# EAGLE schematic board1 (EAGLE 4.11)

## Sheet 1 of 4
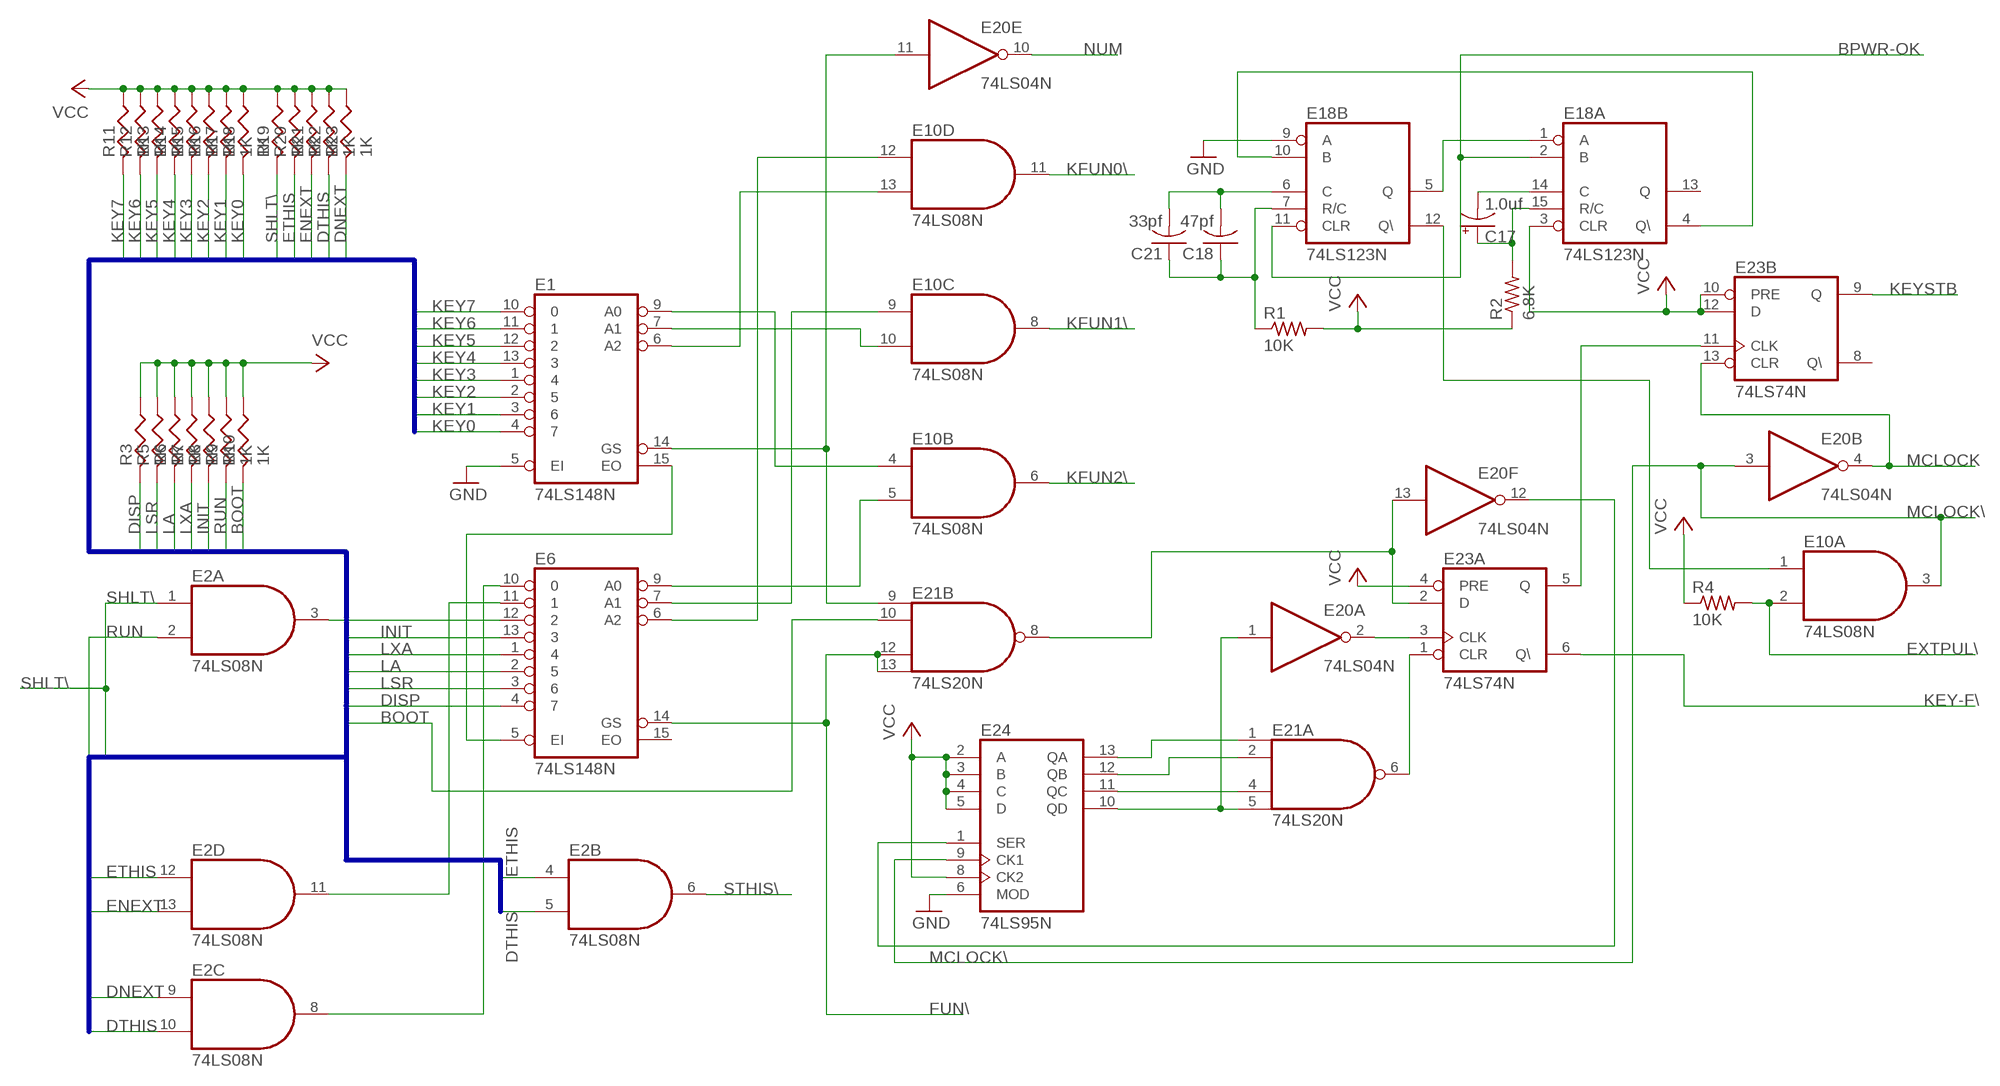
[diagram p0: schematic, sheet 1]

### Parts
C17  1.0uf  CPOL-USE15-5AXIAL  [E15-5]
C18  47pf  C-US050-025X075  [C050-025X075]
C21  33pf  C-US050-025X075  [C050-025X075]
E1  74LS148N  [DIL16]
E2  74LS08N  [DIL14]
E6  74LS148N  [DIL16]
E10  74LS08N  [DIL14]
E18  74LS123N  [DIL16]
E20  74LS04N  [DIL14]
E21  74LS20N  [DIL14]
E23  74LS74N  [DIL14]
E24  74LS95N  [DIL14]
R1  10K  R-US_0207/10  [0207/10]
R2  6.8K  R-US_0207/10  [0207/10]
R3  1K  RESUS-10  [R-10]
R4  10K  R-US_0207/10  [0207/10]
R5  1K  RESUS-10  [R-10]
R6  1K  RESUS-10  [R-10]
R7  1K  RESUS-10  [R-10]
R8  1K  RESUS-10  [R-10]
R9  1K  RESUS-10  [R-10]
R10  1K  RESUS-10  [R-10]
R11  1K  RESUS-10  [R-10]
R12  1K  RESUS-10  [R-10]
R13  1K  RESUS-10  [R-10]
R14  1K  RESUS-10  [R-10]
R15  1K  RESUS-10  [R-10]
R16  1K  RESUS-10  [R-10]
R17  1K  RESUS-10  [R-10]
R18  1K  RESUS-10  [R-10]
R19  1K  RESUS-10  [R-10]
R20  1K  RESUS-10  [R-10]
R21  1K  RESUS-10  [R-10]
R22  1K  RESUS-10  [R-10]
R23  1K  RESUS-10  [R-10]

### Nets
BOOT: E21.10(B:I1) R10.2 ; also sheet 4
BPWR-OK: E18.2(A:B) E18.11(B:CLR) ; also sheet 3
DISP: E6.4 R3.2 ; also sheet 4
DNEXT: E2.9(C:I0) R23.2 ; also sheet 4
DTHIS: E2.5(B:I1) E2.10(C:I1) R22.2 ; also sheet 4
ENEXT: E2.13(D:I1) R21.2 ; also sheet 4
ETHIS: E2.4(B:I0) E2.12(D:I0) R20.2 ; also sheet 4
EXTPUL\: E10.2(A:I1) R4.2 ; also sheet 3
FUN\: E6.14(GS) E21.12(B:I2) E21.13(B:I3) ; also sheet 3
GND [Supply]: E1.5(EI) E18.9(B:A) E24.6(MOD) ; also sheet 2,3,4
INIT: E6.13 R8.2 ; also sheet 4
KEY0: E1.4 R18.2 ; also sheet 4
KEY1: E1.3 R17.2 ; also sheet 4
KEY2: E1.2 R16.2 ; also sheet 4
KEY3: E1.1 R15.2 ; also sheet 4
KEY4: E1.13 R14.2 ; also sheet 4
KEY5: E1.12 R13.2 ; also sheet 4
KEY6: E1.11 R12.2 ; also sheet 4
KEY7: E1.10 R11.2 ; also sheet 4
KEY-F\: E23.6(A:Q\) ; also sheet 3
KEYSTB: E23.9(B:Q) ; also sheet 3
KFUN0\: E10.11(D:O) ; also sheet 3
KFUN1\: E10.8(C:O) ; also sheet 3
KFUN2\: E10.6(B:O) ; also sheet 3
LA: E6.2 R6.2 ; also sheet 4
LSR: E6.3 R5.2 ; also sheet 4
LXA: E6.1 R7.2 ; also sheet 4
MCLOCK: E20.4(B:O) E23.13(B:CLR) ; also sheet 2
MCLOCK\: E10.3(A:O) E20.3(B:I) E24.9(CK1) ; also sheet 3
N$1: E1.6(A2) E10.13(D:I1)
N$2: E1.7(A1) E10.10(C:I1)
N$3: E1.9(A0) E10.4(B:I0)
N$4: E1.14(GS) E20.11(E:I) E21.9(B:I0)
N$5: E6.6(A2) E10.12(D:I0)
N$6: E6.7(A1) E10.9(C:I0)
N$7: E6.9(A0) E10.5(B:I1)
N$8: E1.15(EO) E6.5(EI)
N$9: E21.1(A:I0) E24.13(QA)
N$10: E21.2(A:I1) E24.12(QB)
N$11: E21.4(A:I2) E24.11(QC)
N$12: E20.1(A:I) E21.5(A:I3) E24.10(QD)
N$13: E21.6(A:O) E23.1(A:CLR)
N$14: E20.2(A:O) E23.3(A:CLK)
N$15: E20.13(F:I) E21.8(B:O) E23.2(A:D)
N$16: E20.12(F:O) E24.1(SER)
N$17: E23.5(A:Q) E23.11(B:CLK)
N$18: E18.1(A:A) E18.5(B:Q)
N$19: C18.1 C21.1 E18.7(B:R/C) R1.1
N$20: C17.+ E18.15(A:R/C) R2.2
N$21: C18.2 C21.2 E18.6(B:C)
N$22: C17.- E18.14(A:C)
N$23: E2.3(A:O) E6.12
N$24: E18.4(A:Q\) E18.10(B:B)
N$25: E2.11(D:O) E6.11
N$26: E2.8(C:O) E6.10
N$27: E10.1(A:I0) E18.12(B:Q\)
NUM: E20.10(E:O) ; also sheet 3
RUN: E2.2(A:I1) R9.2 ; also sheet 4
SHLT\: E2.1(A:I0) R19.2 ; also sheet 3,4
STHIS\: E2.6(B:O) ; also sheet 3
VCC [Supply]: E18.3(A:CLR) E23.4(A:PRE) E23.10(B:PRE) E23.12(B:D) E24.2(A) E24.3(B) E24.4(C) E24.5(D) E24.8(CK2) R1.2 R2.1 R3.1 R4.1 R5.1 R6.1 R7.1 R8.1 R9.1 R10.1 R11.1 R12.1 R13.1 R14.1 R15.1 R16.1 R17.1 R18.1 R19.1 R20.1 R21.1 R22.1 R23.1 ; also sheet 2,3
Unconnected: E6.15(EO) E18.13(A:Q) E20.5(C:I) E20.6(C:O) E20.8(D:O) E20.9(D:I) E23.8(B:Q\)

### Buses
KEY[0..7],DISP,LSR,LA,LXA,INIT,RUN,BOOT,HLT\,ETHIS,ENEXT,DTHIS,DNEXT

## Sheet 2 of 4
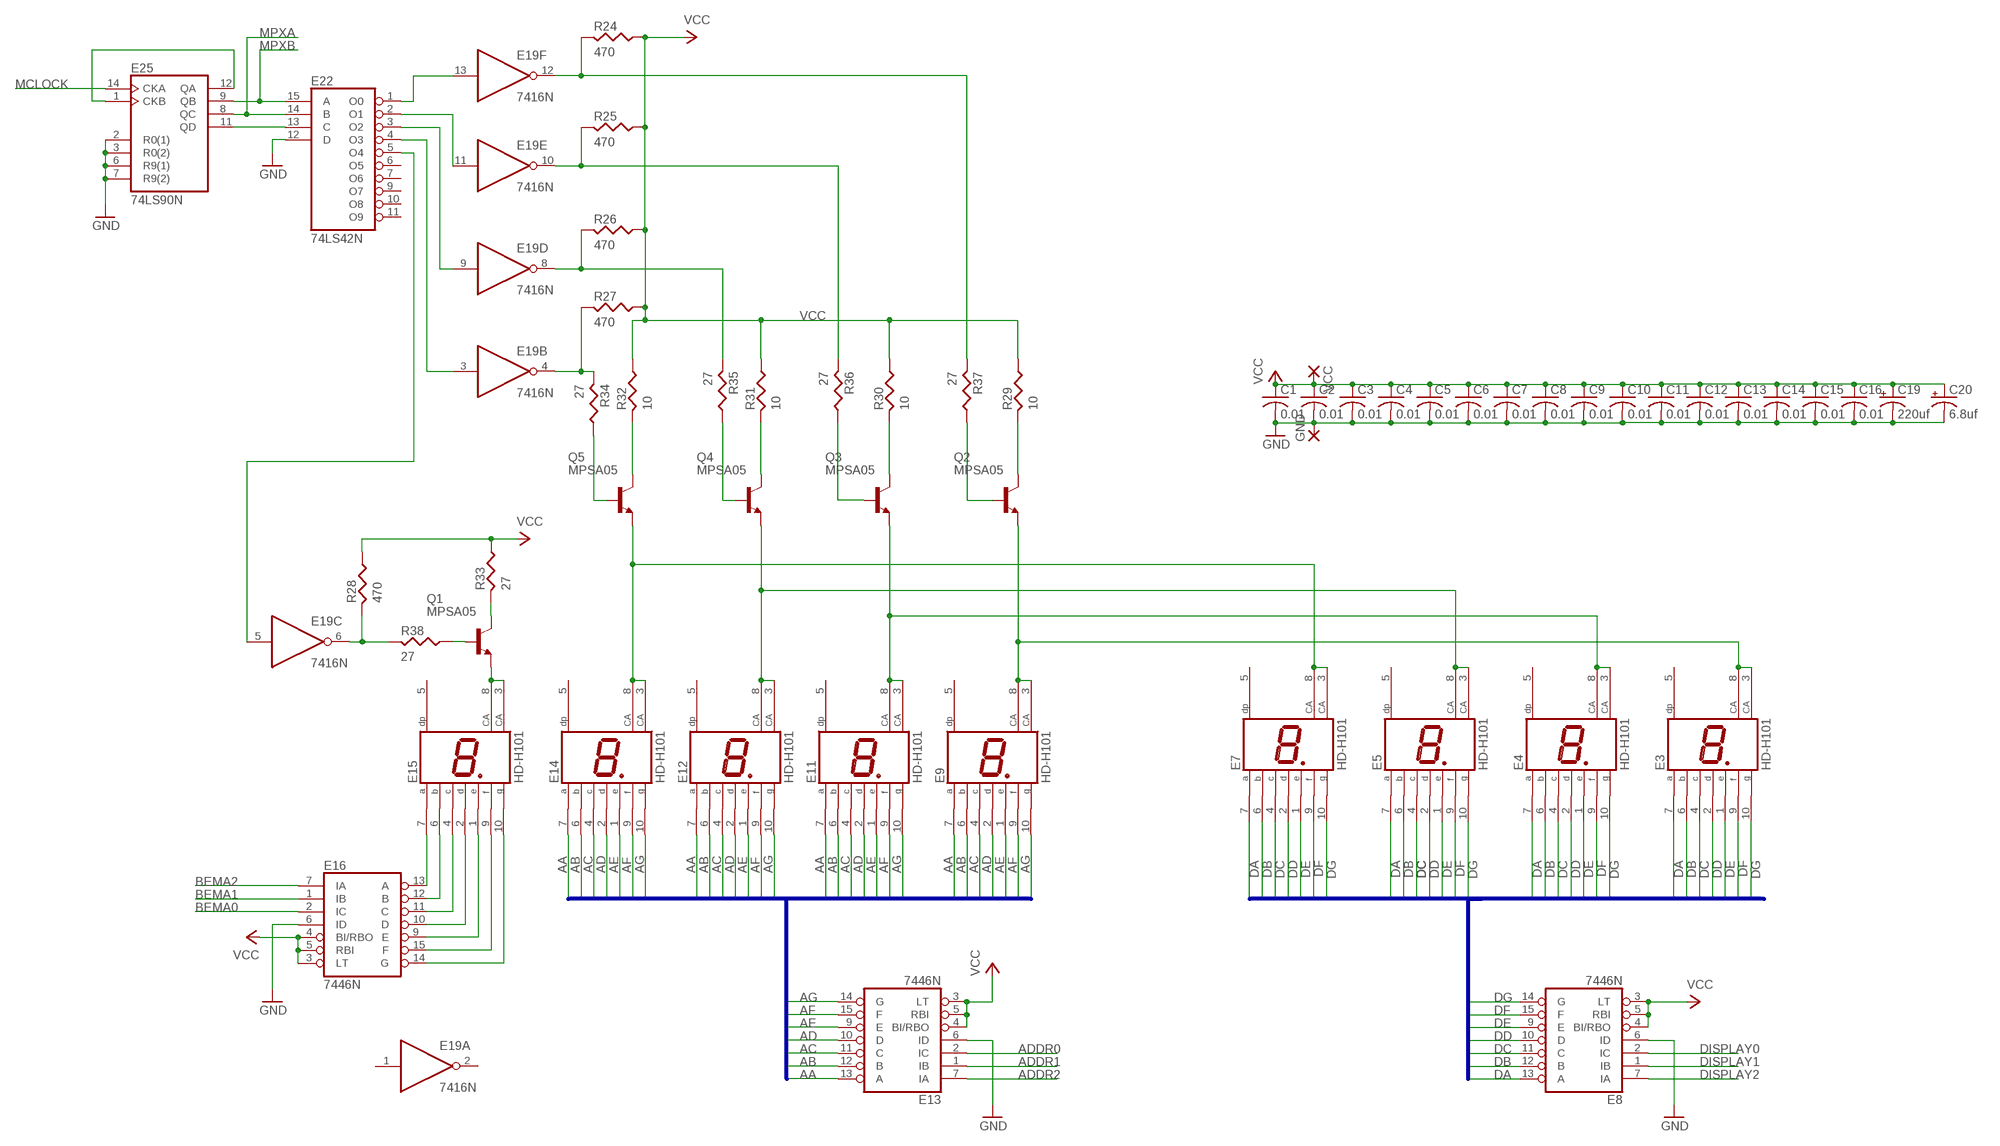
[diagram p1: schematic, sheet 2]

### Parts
C1  0.01  C-US050-025X075  [C050-025X075]
C2  0.01  C-US050-025X075  [C050-025X075]
C3  0.01  C-US050-025X075  [C050-025X075]
C4  0.01  C-US050-025X075  [C050-025X075]
C5  0.01  C-US050-025X075  [C050-025X075]
C6  0.01  C-US050-025X075  [C050-025X075]
C7  0.01  C-US050-025X075  [C050-025X075]
C8  0.01  C-US050-025X075  [C050-025X075]
C9  0.01  C-US050-025X075  [C050-025X075]
C10  0.01  C-US050-025X075  [C050-025X075]
C11  0.01  C-US050-025X075  [C050-025X075]
C12  0.01  C-US050-025X075  [C050-025X075]
C13  0.01  C-US050-025X075  [C050-025X075]
C14  0.01  C-US050-025X075  [C050-025X075]
C15  0.01  C-US050-025X075  [C050-025X075]
C16  0.01  C-US050-025X075  [C050-025X075]
C19  220uf  CPOL-USE22-6AXIAL  [E22-6]
C20  6.8uf  CPOL-USE22-6AXIAL  [E22-6]
E3  HD-H101  [HDSP-M]
E4  HD-H101  [HDSP-M]
E5  HD-H101  [HDSP-M]
E7  HD-H101  [HDSP-M]
E8  7446N  [DIL16]
E9  HD-H101  [HDSP-M]
E11  HD-H101  [HDSP-M]
E12  HD-H101  [HDSP-M]
E13  7446N  [DIL16]
E14  HD-H101  [HDSP-M]
E15  HD-H101  [HDSP-M]
E16  7446N  [DIL16]
E19  7416N  [DIL14]
E22  74LS42N  [DIL16]
E25  74LS90N  [DIL14]
GND  3,81/1,4  [3,81/1,4]
Q1  MPSA05  2N2222A  [TO18]
Q2  MPSA05  2N2222A  [TO18]
Q3  MPSA05  2N2222A  [TO18]
Q4  MPSA05  2N2222A  [TO18]
Q5  MPSA05  2N2222A  [TO18]
R24  470  RESUS-10  [R-10]
R25  470  RESUS-10  [R-10]
R26  470  RESUS-10  [R-10]
R27  470  RESUS-10  [R-10]
R28  470  RESUS-10  [R-10]
R29  10  RESUS-10  [R-10]
R30  10  RESUS-10  [R-10]
R31  10  RESUS-10  [R-10]
R32  10  RESUS-10  [R-10]
R33  27  RESUS-10  [R-10]
R34  27  RESUS-10  [R-10]
R35  27  RESUS-10  [R-10]
R36  27  RESUS-10  [R-10]
R37  27  RESUS-10  [R-10]
R38  27  RESUS-10  [R-10]
VCC  3,81/1,4  [3,81/1,4]

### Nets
AA: E9.7(A) E11.7(A) E12.7(A) E13.13(A) E14.7(A)
AB: E9.6(B) E11.6(B) E12.6(B) E13.12(B) E14.6(B)
AC: E9.4(C) E11.4(C) E12.4(C) E13.11(C) E14.4(C)
AD: E9.2(D) E11.2(D) E12.2(D) E13.10(D) E14.2(D)
ADDR0: E13.2(IC) ; also sheet 3
ADDR1: E13.1(IB) ; also sheet 3
ADDR2: E13.7(IA) ; also sheet 3
AE: E9.1(E) E11.1(E) E12.1(E) E13.9(E) E14.1(E)
AF: E9.9(F) E11.9(F) E12.9(F) E13.15(F) E14.9(F)
AG: E9.10(G) E11.10(G) E12.10(G) E13.14(G) E14.10(G)
BEMA0: E16.2(IC) ; also sheet 3
BEMA1: E16.1(IB) ; also sheet 3
BEMA2: E16.7(IA) ; also sheet 3
DA: E3.7(A) E4.7(A) E5.7(A) E7.7(A) E8.13(A)
DB: E3.6(B) E4.6(B) E5.6(B) E7.6(B) E8.12(B)
DC: E3.4(C) E4.4(C) E5.4(C) E7.4(C) E8.11(C)
DD: E3.2(D) E4.2(D) E5.2(D) E7.2(D) E8.10(D)
DE: E3.1(E) E4.1(E) E5.1(E) E7.1(E) E8.9(E)
DF: E3.9(F) E4.9(F) E5.9(F) E7.9(F) E8.15(F)
DG: E3.10(G) E4.10(G) E5.10(G) E7.10(G) E8.14(G)
DISPLAY0: E8.2(IC) ; also sheet 3
DISPLAY1: E8.1(IB) ; also sheet 3
DISPLAY2: E8.7(IA) ; also sheet 3
GND [Supply]: C1.2 C2.2 C3.2 C4.2 C5.2 C6.2 C7.2 C8.2 C9.2 C10.2 C11.2 C12.2 C13.2 C14.2 C15.2 C16.2 C19.- C20.- E8.6(ID) E13.6(ID) E16.6(ID) E22.12(D) E25.2(R0(1)) E25.3(R0(2)) E25.6(R9(1)) E25.7(R9(2)) GND.1(P) ; also sheet 1,3,4
MCLOCK: E25.14(CKA) ; also sheet 1
MPXA: E22.14(B) E25.8(QC) ; also sheet 3
MPXB: E22.15(A) E25.9(QB) ; also sheet 3
N$28: E15.7(A) E16.13(A)
N$29: E15.6(B) E16.12(B)
N$30: E15.4(C) E16.11(C)
N$31: E15.2(D) E16.10(D)
N$32: E15.1(E) E16.9(E)
N$33: E15.9(F) E16.15(F)
N$34: E15.10(G) E16.14(G)
N$35: E19.12(F:O) R24.2 R37.2
N$36: E19.10(E:O) R25.2 R36.2
N$37: E22.13(C) E25.11(QD)
N$39: E25.1(CKB) E25.12(QA)
N$40: E19.8(D:O) R26.2 R35.2
N$41: E19.13(F:I) E22.1(O0)
N$42: E19.11(E:I) E22.2(O1)
N$43: E19.9(D:I) E22.3(O2)
N$44: E19.3(B:I) E22.4(O3)
N$45: E19.5(C:I) E22.5(O4)
N$46: E19.4(B:O) R27.2 R34.2
N$47: E15.3(CA) E15.8(CA) Q1.1(E)
N$48: Q2.3(C) R29.2
N$49: Q3.3(C) R30.2
N$50: Q4.3(C) R31.2
N$51: Q5.3(C) R32.2
N$52: Q1.3(C) R33.2
N$53: Q1.2(B) R38.1
N$54: E7.3(CA) E7.8(CA) E14.3(CA) E14.8(CA) Q5.1(E)
N$55: Q5.2(B) R34.1
N$56: Q4.2(B) R35.1
N$57: Q3.2(B) R36.1
N$58: Q2.2(B) R37.1
N$59: E19.6(C:O) R28.2 R38.2
N$60: E5.3(CA) E5.8(CA) E12.3(CA) E12.8(CA) Q4.1(E)
N$61: E4.3(CA) E4.8(CA) E11.3(CA) E11.8(CA) Q3.1(E)
N$62: E3.3(CA) E3.8(CA) E9.3(CA) E9.8(CA) Q2.1(E)
VCC [Supply]: C1.1 C2.1 C3.1 C4.1 C5.1 C6.1 C7.1 C8.1 C9.1 C10.1 C11.1 C12.1 C13.1 C14.1 C15.1 C16.1 C19.+ C20.+ E8.3(LT) E8.4(BI/RBO) E8.5(RBI) E13.3(LT) E13.4(BI/RBO) E13.5(RBI) E16.3(LT) E16.4(BI/RBO) E16.5(RBI) R24.1 R25.1 R26.1 R27.1 R28.1 R29.1 R30.1 R31.1 R32.1 R33.1 VCC.1(P) ; also sheet 1,3
Unconnected: E3.5(DP) E4.5(DP) E5.5(DP) E7.5(DP) E9.5(DP) E11.5(DP) E12.5(DP) E14.5(DP) E15.5(DP) E22.6(O5) E22.7(O6) E22.9(O7) E22.10(O8) E22.11(O9)

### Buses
ASEG:AA,AB,AC,AD,AE,AF,AG
DSEG:DA,DB,DC,DD,DE,DF,DG

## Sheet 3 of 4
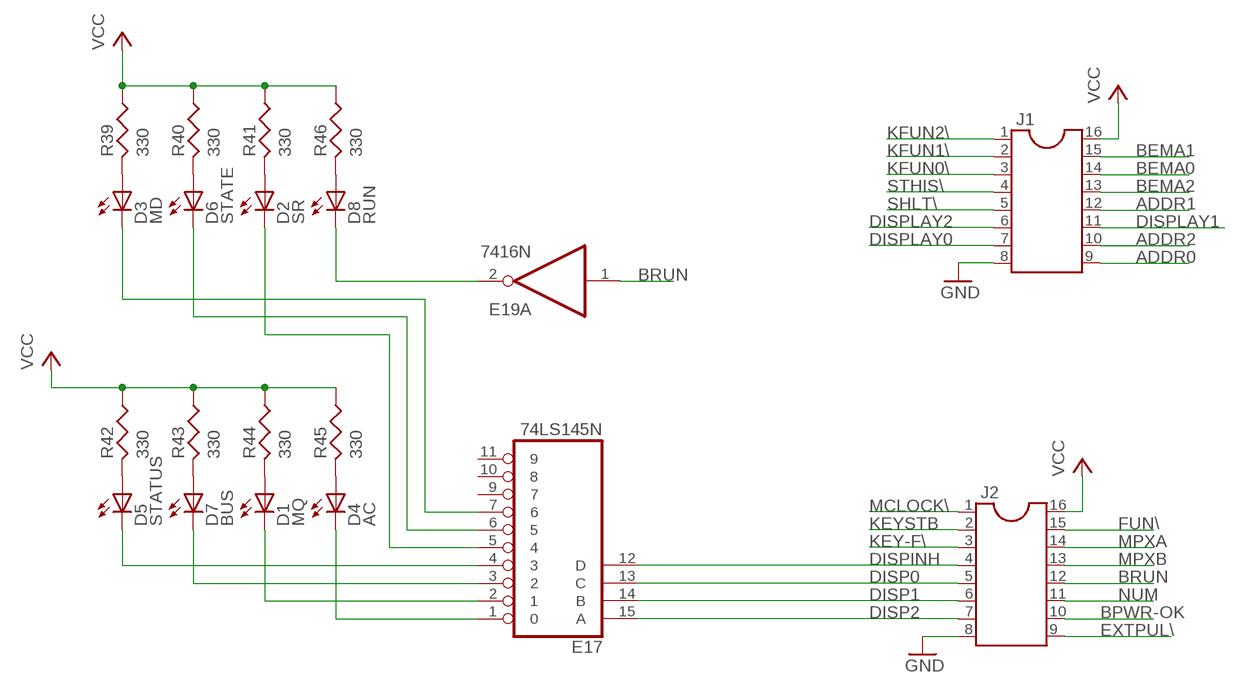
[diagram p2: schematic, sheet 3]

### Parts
D1  MQ  LED5MM  [LED5MM]
D2  SR  LED5MM  [LED5MM]
D3  MD  LED5MM  [LED5MM]
D4  AC  LED5MM  [LED5MM]
D5  STATUS  LED5MM  [LED5MM]
D6  STATE  LED5MM  [LED5MM]
D7  BUS  LED5MM  [LED5MM]
D8  RUN  LED5MM  [LED5MM]
E17  74LS145N  [DIL16]
J1  DIL16S  [SOCKED-16]
J2  DIL16S  [SOCKED-16]
R39  330  RESUS-10  [R-10]
R40  330  RESUS-10  [R-10]
R41  330  RESUS-10  [R-10]
R42  330  RESUS-10  [R-10]
R43  330  RESUS-10  [R-10]
R44  330  RESUS-10  [R-10]
R45  330  RESUS-10  [R-10]
R46  330  RESUS-10  [R-10]

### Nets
ADDR0: J1.9 ; also sheet 2
ADDR1: J1.12 ; also sheet 2
ADDR2: J1.10 ; also sheet 2
BEMA0: J1.14 ; also sheet 2
BEMA1: J1.15 ; also sheet 2
BEMA2: J1.13 ; also sheet 2
BPWR-OK: J2.10 ; also sheet 1
BRUN: E19.1(A:I) J2.12
DISP0: E17.13(C) J2.5
DISP1: E17.14(B) J2.6
DISP2: E17.15(A) J2.7
DISPINH: E17.12(D) J2.4
DISPLAY0: J1.7 ; also sheet 2
DISPLAY1: J1.11 ; also sheet 2
DISPLAY2: J1.6 ; also sheet 2
EXTPUL\: J2.9 ; also sheet 1
FUN\: J2.15 ; also sheet 1
GND [Supply]: J1.8 J2.8 ; also sheet 1,2,4
KEY-F\: J2.3 ; also sheet 1
KEYSTB: J2.2 ; also sheet 1
KFUN0\: J1.3 ; also sheet 1
KFUN1\: J1.2 ; also sheet 1
KFUN2\: J1.1 ; also sheet 1
MCLOCK\: J2.1 ; also sheet 1
MPXA: J2.14 ; also sheet 2
MPXB: J2.13 ; also sheet 2
N$38: D3.A R39.2
N$63: D6.A R40.2
N$64: D2.A R41.2
N$65: D5.A R42.2
N$66: D7.A R43.2
N$67: D1.A R44.2
N$68: D4.A R45.2
N$69: D8.A R46.2
N$70: D8.K(C) E19.2(A:O)
N$71: D4.K(C) E17.1
N$72: D1.K(C) E17.2
N$73: D7.K(C) E17.3
N$74: D5.K(C) E17.4
N$75: D2.K(C) E17.5
N$76: D6.K(C) E17.6
N$77: D3.K(C) E17.7
NUM: J2.11 ; also sheet 1
SHLT\: J1.5 ; also sheet 1,4
STHIS\: J1.4 ; also sheet 1
VCC [Supply]: J1.16 J2.16 R39.1 R40.1 R41.1 R42.1 R43.1 R44.1 R45.1 R46.1 ; also sheet 1,2
Unconnected: E17.9 E17.10 E17.11

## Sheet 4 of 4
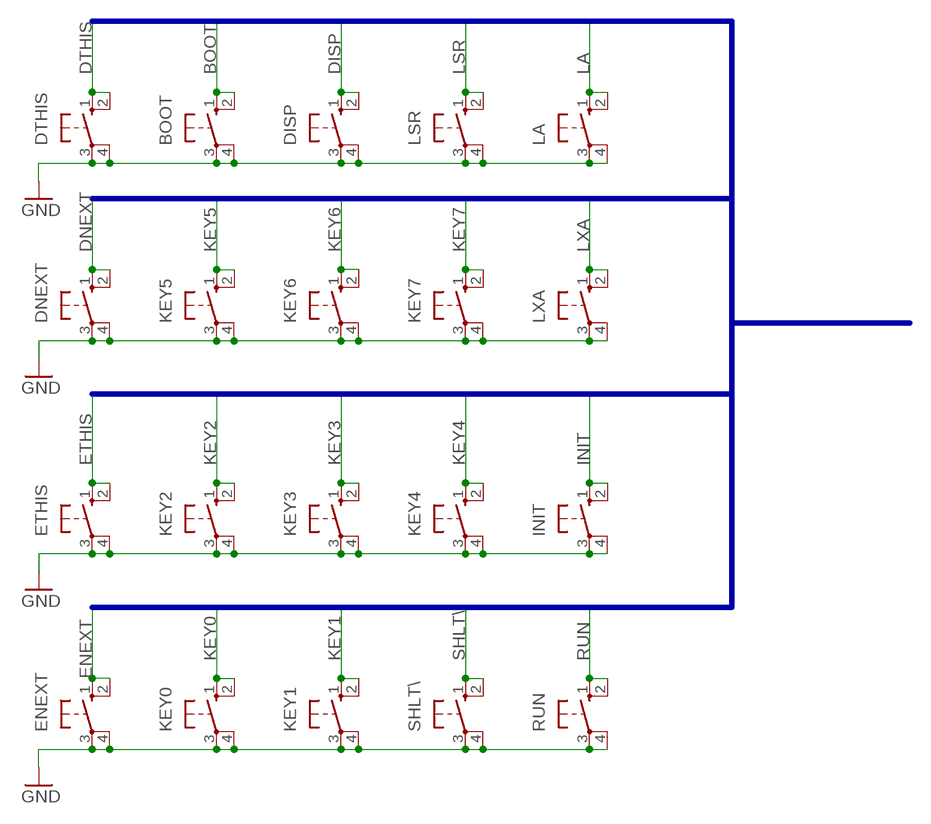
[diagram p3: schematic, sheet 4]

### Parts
BOOT  40-XX  [B3F-40XX]
DISP  40-XX  [B3F-40XX]
DNEXT  40-XX  [B3F-40XX]
DTHIS  40-XX  [B3F-40XX]
ENEXT  40-XX  [B3F-40XX]
ETHIS  40-XX  [B3F-40XX]
INIT  40-XX  [B3F-40XX]
KEY0  40-XX  [B3F-40XX]
KEY1  40-XX  [B3F-40XX]
KEY2  40-XX  [B3F-40XX]
KEY3  40-XX  [B3F-40XX]
KEY4  40-XX  [B3F-40XX]
KEY5  40-XX  [B3F-40XX]
KEY6  40-XX  [B3F-40XX]
KEY7  40-XX  [B3F-40XX]
LA  40-XX  [B3F-40XX]
LSR  40-XX  [B3F-40XX]
LXA  40-XX  [B3F-40XX]
RUN  40-XX  [B3F-40XX]
SHLT\  40-XX  [B3F-40XX]

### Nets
BOOT: BOOT.1(S) BOOT.2(S1) ; also sheet 1
DISP: DISP.1(S) DISP.2(S1) ; also sheet 1
DNEXT: DNEXT.1(S) DNEXT.2(S1) ; also sheet 1
DTHIS: DTHIS.1(S) DTHIS.2(S1) ; also sheet 1
ENEXT: ENEXT.1(S) ENEXT.2(S1) ; also sheet 1
ETHIS: ETHIS.1(S) ETHIS.2(S1) ; also sheet 1
GND [Supply]: BOOT.3(P) BOOT.4(P1) DISP.3(P) DISP.4(P1) DNEXT.3(P) DNEXT.4(P1) DTHIS.3(P) DTHIS.4(P1) ENEXT.3(P) ENEXT.4(P1) ETHIS.3(P) ETHIS.4(P1) INIT.3(P) INIT.4(P1) KEY0.3(P) KEY0.4(P1) KEY1.3(P) KEY1.4(P1) KEY2.3(P) KEY2.4(P1) KEY3.3(P) KEY3.4(P1) KEY4.3(P) KEY4.4(P1) KEY5.3(P) KEY5.4(P1) KEY6.3(P) KEY6.4(P1) KEY7.3(P) KEY7.4(P1) LA.3(P) LA.4(P1) LSR.3(P) LSR.4(P1) LXA.3(P) LXA.4(P1) RUN.3(P) RUN.4(P1) SHLT\.3(P) SHLT\.4(P1) ; also sheet 1,2,3
INIT: INIT.1(S) INIT.2(S1) ; also sheet 1
KEY0: KEY0.1(S) KEY0.2(S1) ; also sheet 1
KEY1: KEY1.1(S) KEY1.2(S1) ; also sheet 1
KEY2: KEY2.1(S) KEY2.2(S1) ; also sheet 1
KEY3: KEY3.1(S) KEY3.2(S1) ; also sheet 1
KEY4: KEY4.1(S) KEY4.2(S1) ; also sheet 1
KEY5: KEY5.1(S) KEY5.2(S1) ; also sheet 1
KEY6: KEY6.1(S) KEY6.2(S1) ; also sheet 1
KEY7: KEY7.1(S) KEY7.2(S1) ; also sheet 1
LA: LA.1(S) LA.2(S1) ; also sheet 1
LSR: LSR.1(S) LSR.2(S1) ; also sheet 1
LXA: LXA.1(S) LXA.2(S1) ; also sheet 1
RUN: RUN.1(S) RUN.2(S1) ; also sheet 1
SHLT\: SHLT\.1(S) SHLT\.2(S1) ; also sheet 1,3

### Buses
KEY[0..7],DISP,LSR,LA,LXA,INIT,RUN,BOOT,HLT\,ETHIS,ENEXT,DTHIS,DNEXT

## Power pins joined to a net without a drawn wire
GND: E1.8(GND) E2.7(P:GND) E6.8(GND) E8.8(GND) E10.7(P:GND) E13.8(GND) E16.8(GND) E17.8(GND) E18.8(P:GND) E19.7(P:GND) E20.7(P:GND) E21.7(P:GND) E22.8(GND) E23.7(P:GND) E24.7(GND) E25.10(GND)
VCC: E1.16(VCC) E2.14(P:VCC) E6.16(VCC) E8.16(VCC) E10.14(P:VCC) E13.16(VCC) E16.16(VCC) E17.16(VCC) E18.16(P:VCC) E19.14(P:VCC) E20.14(P:VCC) E21.14(P:VCC) E22.16(VCC) E23.14(P:VCC) E24.14(VCC) E25.5(VCC)

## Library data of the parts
BOOT DISP DNEXT DTHIS ENEXT ETHIS INIT KEY0 KEY1-KEY7 LA LSR LXA RUN SHLT\ = switch-omron:40-XX: OMRON SWITCH
C1-C16 C18 C21 = rcl:C-US: CAPACITOR, American symbol
C17 C19 C20 = rcl:CPOL-US: POLARIZED CAPACITOR, American symbol
D1-D8 = led:LED: LED
E1 E6 = 74xx-us:74*148: 10-line to 4-line and 8-line to 3-line PRIORITY ENCODER
E2 E10 = 74xx-us:74*08: Quad 2-input AND gate
E3-E5 E7 E9 E11 E12 E14 E15 = display-hp:HD-H101: LED DISPLAY 1-character 7 segment, decimal point right
E8 E13 E16 = 74xx-us:74*46: BCD to seven segment DECODER/DRIVER, open collector
E17 = 74xx-us:74*145: BCD to decimal DECODER/DRIVER
E18 = 74xx-us:74*123: Retriggerable monostable MULTIVIBRATOR
E19 = 74xx-us:74*16: Hex INVERTER, open collector, high-voltage
E20 = 74xx-us:74*04: Hex INVERTER
E21 = 74xx-us:74*20: Dual 4-input NAND gate
E22 = 74xx-us:74*42: 4-line to 10-line DECODER (1-of-10)
E23 = 74xx-us:74*74: Dual D type positive edge triggered FLIP FLOP, preset and clear
E24 = 74xx-us:74*95: 4-bit parallel access SHIFT REGISTER
E25 = 74xx-us:74*90: Decade, divide by twelve and binary COUNTER
GND VCC = wirepad:3,81/1,4: THROUGH-HOLE PAD
J1 J2 = ic-package:DIL16: Dual In Line
Q1-Q5 = transistor-npn:2N2222*: NPN Transistor
R1 R2 R4 = rcl:R-US_: RESISTOR, American symbol
R3 R5-R46 = discrete:RESUS-10

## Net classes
1 Supply: width 0.635 mm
